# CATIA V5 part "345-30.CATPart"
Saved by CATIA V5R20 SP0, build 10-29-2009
Part number: 345-30
Definition: NONE
Nomenclature: 345-30
Source: Unknown
Description: 345-30  
Bounding box of the stored display mesh (mm): x 0 to 72, y -36 to 36, z -36 to 36
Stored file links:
  C:\Users\Utente\Desktop\IO LAVORO\3D X SITO CF\X SITO\345-346\345-30.CATPart
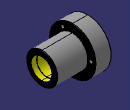
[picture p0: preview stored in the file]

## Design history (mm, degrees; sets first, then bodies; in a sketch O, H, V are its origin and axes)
Body1 "345-30" (main body)
  Solid1: solid without history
